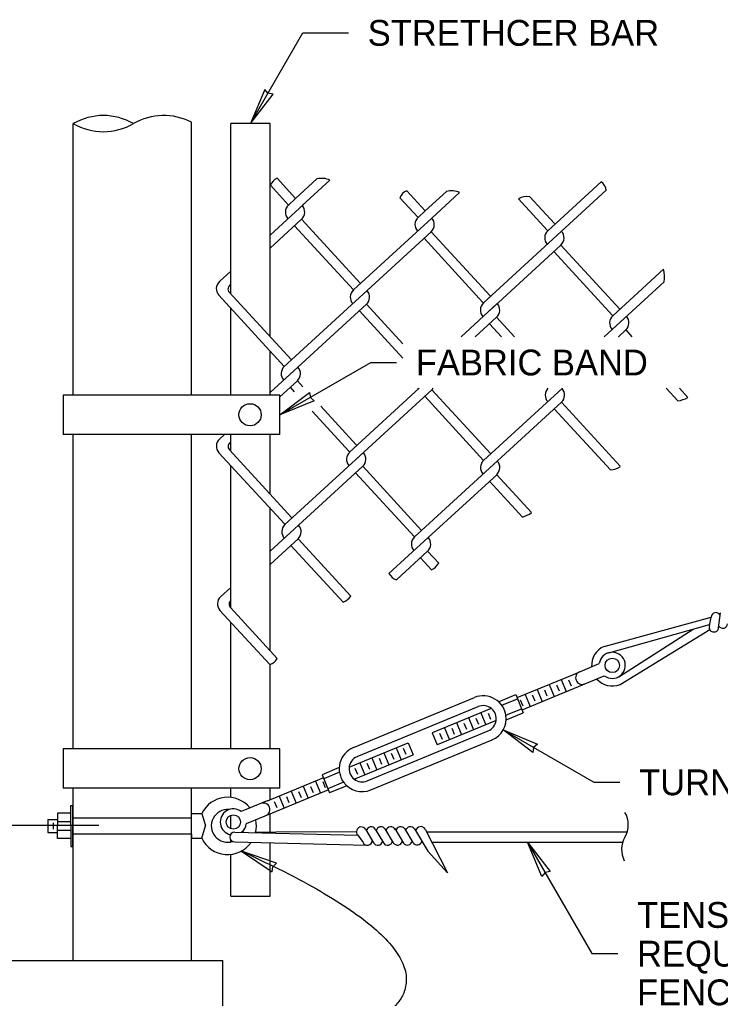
# Model space of a CAD drawing. Extents: x 99862 to 104211, y 98939 to 105076.
# Drawn here: x 100382 to 100816, y 103475 to 104082 of the extents above; entities that cross this region are included whole.
import ezdxf

# ---------------------------------------------------------------- set-up
doc = ezdxf.new("R2010")
doc.units = 0
for name, color, linetype in [('Level 15', 7, 'Continuous'), ('Level 2', 7, 'Continuous'), ('Level 20', 7, 'Continuous'), ('Level 4', 7, 'Continuous'), ('Level 7', 7, 'Continuous')]:
    doc.layers.add(name, color=color, linetype=linetype)

msp = doc.modelspace()

# ---------------------------------------------------------------- linework, layer by layer
at = {"layer": 'Level 15'}
for p, q in [((100524.69, 104017.94), (100557.19, 104074.23)), ((100557.19, 104074.23), (100573.19, 104074.23)), ((100569.42, 104074.23), (100585.42, 104074.23)), ((100542.99, 103837.25), (100599.28, 103869.75)), ((100599.28, 103869.75), (100615.28, 103869.75)), ((100681.43, 103641.84), (100737.72, 103609.34)), ((100737.72, 103609.34), (100753.72, 103609.34)), ((100430.77, 103582.48), (100322.08, 103582.48)), ((100696.53, 103572.2), (100736.45, 103503.07)), ((100736.45, 103503.07), (100752.45, 103503.07))]:
    msp.add_line(p, q, dxfattribs=at)
for points in [[(100524.69, 104017.94), (100538.69, 104036.22), (100535.57, 104036.79), (100533.52, 104039.2)], [(100542.99, 103837.25), (100561.27, 103851.25), (100561.84, 103848.13), (100564.25, 103846.08)], [(100681.43, 103641.84), (100702.69, 103633.01), (100700.29, 103630.95), (100699.71, 103627.84)], [(100696.53, 103572.2), (100710.53, 103553.93), (100707.42, 103553.35), (100705.36, 103550.94)], [(100519.1, 103566.7), (100538.16, 103553.78), (100538.56, 103556.92), (100540.84, 103559.11)]]:
    msp.add_lwpolyline(points, close=True, dxfattribs=at)
msp.add_open_spline([(100519.1, 103566.7), (100649.54, 103507.21), (100577.71, 103432.29), (100658.71, 103432.29)], degree=2, dxfattribs=at)
at = {"layer": 'Level 2'}
for p, q in [((100744.06, 103693.66), (100810.43, 103711.84)), ((100809.29, 103706.44), (100810.43, 103711.84)), ((100815.02, 103705.1), (100816.12, 103714.46)), ((100746.89, 103689.71), (100809.45, 103707.21)), ((100753.09, 103674.83), (100799.33, 103704.38)), ((100754.05, 103670.1), (100809.54, 103704.08)), ((100724.98, 103676.32), (100741, 103682.95)), ((100690, 103661.86), (100724.98, 103676.32)), ((100728.09, 103668.82), (100744.11, 103675.44)), ((100709.97, 103670.12), (100713.07, 103662.61)), ((100714.5, 103669.79), (100716.05, 103666.04)), ((100717.48, 103673.22), (100720.58, 103665.71)), ((100722.01, 103672.9), (100723.56, 103669.14)), ((100678.58, 103659.33), (100689.23, 103663.74)), ((100689.23, 103663.74), (100693.88, 103652.48)), ((100693.11, 103654.35), (100728.09, 103668.82)), ((100694.96, 103663.91), (100698.06, 103656.4)), ((100699.49, 103663.58), (100701.04, 103659.83)), ((100702.46, 103667.01), (100705.57, 103659.51)), ((100706.99, 103666.69), (100708.54, 103662.93)), ((100588.54, 103630.89), (100663.6, 103661.93)), ((100691.98, 103660.48), (100693.53, 103656.73)), ((100590.87, 103625.26), (100665.93, 103656.3)), ((100673.98, 103655.23), (100637.48, 103640.14)), ((100667.5, 103652.55), (100670.61, 103645.05)), ((100672.03, 103652.23), (100673.58, 103648.48)), ((100683.23, 103648.07), (100693.88, 103652.48)), ((100677.09, 103647.73), (100640.58, 103632.63)), ((100652.49, 103646.35), (100655.59, 103638.84)), ((100657.02, 103646.02), (100658.57, 103642.27)), ((100660, 103649.45), (100663.1, 103641.94)), ((100664.52, 103649.13), (100666.08, 103645.37)), ((100597.07, 103610.25), (100672.2, 103641.31)), ((100637.48, 103640.14), (100640.58, 103632.63)), ((100642.01, 103639.81), (100643.56, 103636.06)), ((100644.98, 103643.24), (100648.09, 103635.74)), ((100649.51, 103642.92), (100651.06, 103639.16)), ((100585.96, 103618.83), (100622.46, 103633.93)), ((100599.4, 103604.62), (100674.54, 103635.69)), ((100622.46, 103633.93), (100625.57, 103626.42)), ((100589.06, 103611.33), (100625.57, 103626.42)), ((100607.45, 103627.72), (100610.55, 103620.22)), ((100611.98, 103627.4), (100613.53, 103623.64)), ((100614.96, 103630.83), (100618.06, 103623.32)), ((100619.49, 103630.5), (100621.04, 103626.75)), ((100592.44, 103621.51), (100595.54, 103614.01)), ((100596.97, 103621.19), (100598.52, 103617.44)), ((100599.94, 103624.62), (100603.05, 103617.11)), ((100604.47, 103624.29), (100606.02, 103620.54)), ((100579.77, 103618.48), (100569.12, 103614.07)), ((100589.46, 103618.09), (100591.01, 103614.33)), ((100569.9, 103612.19), (100534.96, 103597.75)), ((100564.98, 103610.16), (100568.09, 103602.65)), ((100569.12, 103614.07), (100573.78, 103602.81)), ((100569.51, 103609.84), (100571.06, 103606.08)), ((100573, 103604.69), (100538.06, 103590.24)), ((100549.97, 103603.95), (100553.07, 103596.45)), ((100554.5, 103603.63), (100556.05, 103599.88)), ((100557.48, 103607.06), (100560.58, 103599.55)), ((100562, 103606.73), (100563.56, 103602.98)), ((100584.43, 103607.22), (100573.78, 103602.81)), ((100535.04, 103597.78), (100519.02, 103591.16)), ((100539.49, 103597.42), (100541.04, 103593.67)), ((100542.46, 103600.85), (100545.57, 103593.34)), ((100546.99, 103600.52), (100548.54, 103596.77)), ((100405.1, 103590.16), (100405.1, 103582.28)), ((100538.15, 103590.27), (100522.13, 103583.65)), ((100399.13, 103586.34), (100399.13, 103578.22)), ((100399.13, 103586.34), (100405.1, 103586.34)), ((100402.29, 103584.31), (100402.29, 103580.25)), ((100405.15, 103584.99), (100413.32, 103584.99)), ((100414.77, 103587.37), (100488.04, 103587.37)), ((100494.52, 103589.91), (100496.87, 103582.29)), ((100399.13, 103578.22), (100405.1, 103578.22)), ((100405.05, 103579.58), (100413.32, 103579.58)), ((100405.1, 103574.41), (100405.1, 103582.28)), ((100494.52, 103574.68), (100496.87, 103582.29)), ((100515.09, 103578.44), (100591.19, 103576.6)), ((100527.94, 103578.52), (100540.61, 103578.6)), ((100540.61, 103578.6), (100590.46, 103578.91)), ((100596.06, 103580.22), (100600.99, 103571.82)), ((100602.1, 103580.35), (100607.17, 103571.75)), ((100608.11, 103580.51), (100613.27, 103571.87)), ((100614.14, 103580.63), (100619.62, 103571.57)), ((100620.27, 103580.61), (100625.44, 103572.01)), ((100626.44, 103580.55), (100634.69, 103566.63)), ((100633.02, 103580.22), (100646.84, 103553.24)), ((100633.87, 103578.55), (100758.28, 103578.54)), ((100488.04, 103577.21), (100414.77, 103577.21)), ((100514.94, 103572.34), (100596.49, 103570.37)), ((100591.2, 103576.58), (100594.51, 103571.94)), ((100637.12, 103572.21), (100755.52, 103572.2)), ((100634.69, 103566.63), (100646.84, 103553.24))]:
    msp.add_line(p, q, dxfattribs=at)
for points in [[(100680.54, 103657.15), (100690.28, 103661.18)], [(100683.08, 103651), (100692.82, 103655.03)], [(100579.93, 103615.54), (100570.18, 103611.51)], [(100582.47, 103609.4), (100572.72, 103605.37)], [(100413.32, 103582.28), (100413.32, 103590.16), (100405.1, 103590.16)], [(100413.32, 103590.16), (100413.32, 103595.03), (100414.54, 103595.03)], [(100413.32, 103574.41), (100413.32, 103569.54), (100414.54, 103569.54), (100414.54, 103595.03)], [(100488.04, 103587.37), (100488.04, 103589.91), (100494.52, 103589.91)], [(100413.32, 103582.28), (100413.32, 103574.41), (100405.1, 103574.41)], [(100488.04, 103577.21), (100488.04, 103574.68), (100494.52, 103574.68)]]:
    msp.add_lwpolyline(points, dxfattribs=at)
for centre in [(100749.05, 103681.88), (100514.08, 103584.72)]:
    msp.add_circle(centre, 4.47, dxfattribs=at)
for centre, radius, start, end in [((100813.37, 103711.66), 2.95, 28.55995, 176.50822), ((100812.1, 103705.54), 2.95, 162.2466, 355.13036), ((100817.52, 103707.87), 2.95, 216.19353, 356.79864), ((100749.05, 103681.88), 12.8, 112.96867, 183.96114), ((100749.05, 103681.88), 8.12, 232.46575, 172.46575), ((100730.37, 103674.16), 4.06, 112.46575, 292.46575), ((100749.05, 103681.88), 12.8, 220.97036, 292.96867), ((100669.03, 103648.79), 14.22, 6.15322, 112.46765), ((100669.03, 103648.79), 8.12, 349.38086, 112.46754), ((100669.03, 103648.79), 14.22, 292.46575, 8.94198), ((100669.03, 103648.79), 8.12, 292.46575, 352.46441), ((100593.97, 103617.75), 14.22, 112.46385, 217.98282), ((100593.97, 103617.75), 8.12, 112.46396, 241.57185), ((100593.97, 103617.75), 14.22, 215.9905, 292.46575), ((100593.97, 103617.75), 8.12, 232.46575, 292.46575), ((100510.58, 103582.29), 17.77, 38.69447, 154.62307), ((100532.75, 103592.44), 4.06, 292.46575, 112.46575), ((100510.58, 103582.29), 10.15, 85.01859, 287.42988), ((100514.08, 103584.72), 8.12, 52.46575, 256.90582), ((100743.6, 103583.03), 15.35, 330, 30), ((100510.58, 103582.29), 17.77, 346.44895, 12.23165), ((100514.92, 103575.39), 3.05, 90.3612, 270.3612), ((100514.08, 103584.72), 8.12, 309.02747, 352.46575), ((100510.58, 103582.29), 10.15, 337.50578, 344.44411), ((100593.49, 103578.6), 3.05, 32.2514, 221.40065), ((100599.58, 103578.64), 3.05, 34.22449, 167.45372), ((100605.67, 103578.67), 3.05, 36.98401, 167.51131), ((100611.77, 103578.71), 3.05, 23.53144, 167.6433), ((100617.86, 103578.75), 3.05, 37.67326, 167.76298), ((100623.96, 103578.79), 3.05, 35.2348, 167.68417), ((100630.3, 103578.83), 3.05, 27.11893, 173.95764), ((100510.58, 103582.29), 17.77, 205.37693, 324.62168), ((100597.22, 103573.33), 3.05, 207.13903, 355.0873), ((100603.62, 103573.37), 3.05, 210.43814, 347.5653), ((100609.73, 103573.41), 3.05, 212.94547, 348.58451), ((100615.89, 103573.45), 3.06, 210.96407, 347.75914), ((100622, 103573.49), 3.05, 218.89033, 347.06072), ((100628.06, 103573.59), 3.05, 211.0453, 345.70958), ((100770.19, 103567.67), 15.35, 150, 206.99342)]:
    msp.add_arc(centre, radius, start, end, dxfattribs=at)
at = {"layer": 'Level 4'}
for p, q in [((100537.07, 103979.67), (100548.31, 103967.42)), ((100541.25, 103984), (100552.73, 103971.48)), ((100565.95, 103983.61), (100552.73, 103971.48)), ((100574.01, 103982.86), (100556.79, 103967.06)), ((100742.18, 103981.81), (100709.12, 103951.47)), ((100621.6, 103976.31), (100633.09, 103963.8)), ((100646.3, 103975.93), (100633.09, 103963.8)), ((100654.36, 103975.18), (100637.15, 103959.38)), ((100745.35, 103976.57), (100669.22, 103906.69)), ((100697.9, 103972.56), (100713.2, 103955.89)), ((100557.57, 103967.77), (100536.92, 103948.82)), ((100552.73, 103971.48), (100548.31, 103967.42)), ((100617.42, 103971.99), (100628.67, 103959.74)), ((100690.87, 103971.35), (100708.78, 103951.83)), ((100633.09, 103963.8), (100628.67, 103959.74)), ((100556.43, 103958.58), (100536.92, 103940.67)), ((100552.01, 103954.53), (100588.52, 103914.74)), ((100556.43, 103958.58), (100592.94, 103918.8)), ((100637.15, 103959.38), (100588.52, 103914.74)), ((100713.2, 103955.89), (100713.54, 103955.52)), ((100636.78, 103950.9), (100550.09, 103871.32)), ((100628.31, 103951.26), (100628.31, 103951.26)), ((100636.78, 103950.9), (100673.3, 103911.12)), ((100708.78, 103951.83), (100709.12, 103951.47)), ((100632.36, 103946.84), (100668.88, 103907.06)), ((100717.24, 103942.63), (100673.27, 103902.27)), ((100708.76, 103942.99), (100708.76, 103942.99)), ((100717.24, 103942.63), (100753.75, 103902.84)), ((100712.82, 103938.57), (100749.33, 103898.79)), ((100512.49, 103926.39), (100505.46, 103919.94)), ((100780.76, 103927.64), (100749.33, 103898.79)), ((100781.16, 103919.86), (100744, 103885.75)), ((100511.55, 103913.31), (100550.09, 103871.32)), ((100505.1, 103911.47), (100545.67, 103867.26)), ((100596.64, 103905.9), (100554.15, 103866.9)), ((100588.16, 103906.27), (100588.16, 103906.27)), ((100596.64, 103905.9), (100619.28, 103881.24)), ((100677.69, 103906.33), (100655.27, 103885.75)), ((100668.88, 103907.06), (100669.22, 103906.69)), ((100673.64, 103910.75), (100669.22, 103906.69)), ((100673.3, 103911.12), (100673.64, 103910.75)), ((100592.22, 103901.85), (100619.28, 103872.37)), ((100677.33, 103897.85), (100664.15, 103885.75)), ((100668.85, 103898.21), (100668.85, 103898.21)), ((100672.91, 103893.79), (100680.3, 103885.75)), ((100677.33, 103897.85), (100688.44, 103885.75)), ((100748.97, 103890.31), (100748.97, 103890.31)), ((100757.45, 103889.95), (100752.87, 103885.75)), ((100757.45, 103889.95), (100761.3, 103885.75)), ((100753.03, 103885.89), (100753.16, 103885.75)), ((100550.09, 103871.32), (100545.67, 103867.26)), ((100554.15, 103866.9), (100536.92, 103851.08)), ((100553.79, 103858.42), (100542.99, 103848.51)), ((100553.79, 103858.42), (100557.21, 103854.69)), ((100549.37, 103854.37), (100551.89, 103851.62)), ((100629.28, 103853.75), (100586.22, 103814.22)), ((100637.19, 103852.86), (100590.28, 103809.8)), ((100628.71, 103853.22), (100628.71, 103853.22)), ((100637.19, 103852.86), (100673.7, 103813.08)), ((100717.91, 103853.65), (100669.28, 103809.02)), ((100718.01, 103853.75), (100717.91, 103853.65)), ((100782.53, 103853.75), (100789.67, 103845.97)), ((100790.68, 103853.75), (100795.93, 103848.02)), ((100717.54, 103845.17), (100630.85, 103765.6)), ((100632.77, 103848.8), (100669.28, 103809.02)), ((100709.06, 103845.53), (100709.06, 103845.53)), ((100717.54, 103845.17), (100754.06, 103805.39)), ((100562.97, 103839.55), (100585.88, 103814.59)), ((100568.29, 103842.62), (100590.3, 103818.64)), ((100713.12, 103841.11), (100747.96, 103803.16)), ((100508.54, 103825.03), (100505.53, 103822.27)), ((100511.61, 103815.64), (100550.16, 103773.65)), ((100590.64, 103818.27), (100586.22, 103814.22)), ((100590.3, 103818.64), (100590.64, 103818.27)), ((100505.16, 103813.79), (100545.74, 103769.59)), ((100594.7, 103813.85), (100546.08, 103769.22)), ((100594.33, 103805.38), (100536.92, 103752.67)), ((100594.33, 103805.38), (100630.85, 103765.6)), ((100589.91, 103801.32), (100626.43, 103761.54)), ((100677.4, 103800.18), (100634.91, 103761.18)), ((100677.4, 103800.18), (100698.95, 103776.7)), ((100672.98, 103796.12), (100693.39, 103773.89)), ((100554.19, 103760.38), (100536.92, 103744.53)), ((100545.71, 103760.75), (100545.71, 103760.75)), ((100554.19, 103760.38), (100586.91, 103724.74)), ((100634.91, 103761.18), (100610.6, 103738.86)), ((100630.85, 103765.6), (100626.43, 103761.54)), ((100549.77, 103756.33), (100582.13, 103721.07)), ((100634.55, 103752.7), (100615.24, 103734.98)), ((100626.07, 103753.06), (100626.07, 103753.06)), ((100630.13, 103748.64), (100637.07, 103741.08)), ((100634.55, 103752.7), (100641.42, 103745.21)), ((100512.49, 103730.25), (100506.17, 103724.45)), ((100512.26, 103717.82), (100541.28, 103686.2)), ((100505.81, 103715.97), (100536.67, 103682.35))]:
    msp.add_line(p, q, dxfattribs=at)
for centre, radius, start, end in [((100544.24, 103976.93), 7.68, 112.93426, 159.03017), ((100568.93, 103971.99), 12, 64.99857, 104.40024), ((100738.11, 103975.78), 7.28, 6.23281, 55.96723), ((100624.59, 103969.24), 7.68, 112.93426, 159.03017), ((100649.29, 103964.3), 12, 64.99857, 104.40024), ((100696.34, 103960.66), 12, 82.53429, 117.102), ((100552.37, 103963), 6, 132.54951, 222.54951), ((100552.37, 103963), 6, 312.54951, 42.54951), ((100632.73, 103955.32), 6, 132.54951, 222.54951), ((100632.73, 103955.32), 6, 312.54951, 42.54951), ((100713.18, 103947.05), 6, 132.54951, 222.54951), ((100713.18, 103947.05), 6, 312.54951, 42.54951), ((100762.61, 103922.8), 18.78, 350.98302, 14.91191), ((100509.52, 103915.52), 6, 132.54951, 222.54951), ((100513.76, 103915.34), 3, 115.01845, 222.54951), ((100592.58, 103910.32), 6, 132.54951, 222.54951), ((100592.58, 103910.32), 6, 312.54951, 42.54951), ((100673.27, 103902.27), 6, 132.54951, 222.54951), ((100673.27, 103902.27), 6, 312.54951, 42.54951), ((100753.39, 103894.37), 6, 132.54951, 222.54951), ((100753.39, 103894.37), 6, 312.54951, 42.54951), ((100549.73, 103862.84), 6, 132.54951, 222.54951), ((100549.73, 103862.84), 6, 312.54951, 42.54951), ((100633.13, 103857.28), 6, 216.04484, 222.54951), ((100633.13, 103857.28), 6, 312.54951, 323.95516), ((100713.49, 103849.59), 6, 136.1739, 222.54951), ((100713.49, 103849.59), 6, 312.54951, 42.54951), ((100787.05, 103864.57), 18.78, 278.01652, 298.22414), ((100509.58, 103817.85), 6, 132.54951, 222.54951), ((100513.82, 103817.67), 3, 116.43008, 222.54951), ((100590.28, 103809.8), 6, 132.54951, 222.54951), ((100590.28, 103809.8), 6, 312.54951, 42.54951), ((100673.34, 103804.6), 6, 132.54951, 222.54951), ((100673.34, 103804.6), 6, 312.54951, 42.54951), ((100745.35, 103821.75), 18.78, 278.01652, 298.22414), ((100690.28, 103786.94), 13.42, 283.39981, 310.25678), ((100550.13, 103764.8), 6, 132.54951, 222.54951), ((100550.13, 103764.8), 6, 312.54951, 42.54951), ((100630.49, 103757.12), 6, 132.54951, 222.54951), ((100630.49, 103757.12), 6, 312.54951, 42.54951), ((100630.23, 103752.63), 13.42, 300.64138, 326.48003), ((100618.01, 103743.01), 8.49, 209.22637, 250.97872), ((100510.23, 103720.03), 6, 132.54951, 222.54951), ((100577.45, 103732.09), 11.97, 293.00373, 322.14624), ((100514.47, 103719.85), 3, 131.26141, 222.54951), ((100533.78, 103690.49), 8.64, 289.52536, 330.19955)]:
    msp.add_arc(centre, radius, start, end, dxfattribs=at)
at = {"layer": 'Level 7'}
for p, q in [((100414.77, 103849.46), (100414.77, 104017.94)), ((100488.06, 103849.46), (100488.06, 104018.78)), ((100536.92, 104017.94), (100512.49, 104017.94)), ((100512.49, 103912.29), (100512.49, 104017.94)), ((100536.92, 103885.68), (100536.92, 104017.94)), ((100512.49, 103849.46), (100512.49, 103903.42)), ((100536.92, 103849.46), (100536.92, 103876.8)), ((100542.99, 103849.46), (100408.63, 103849.46)), ((100408.63, 103849.46), (100408.63, 103825.03)), ((100542.99, 103825.03), (100542.99, 103849.46)), ((100542.99, 103825.03), (100408.63, 103825.03)), ((100414.77, 103630.09), (100414.77, 103825.03)), ((100488.06, 103630.09), (100488.06, 103825.03)), ((100512.49, 103814.69), (100512.49, 103825.03)), ((100536.92, 103788.08), (100536.92, 103825.03)), ((100512.49, 103717.57), (100512.49, 103805.82)), ((100536.92, 103690.95), (100536.92, 103779.2)), ((100512.49, 103630.09), (100512.49, 103708.69)), ((100536.92, 103630.09), (100536.92, 103682.44)), ((100542.99, 103630.09), (100408.63, 103630.09)), ((100408.63, 103630.09), (100408.63, 103605.66)), ((100542.99, 103605.66), (100542.99, 103630.09)), ((100542.99, 103605.66), (100408.63, 103605.66)), ((100414.77, 103498.91), (100414.77, 103605.66)), ((100488.06, 103498.91), (100488.06, 103605.66)), ((100512.49, 103599.96), (100512.49, 103605.66)), ((100536.92, 103598.56), (100536.92, 103605.66)), ((100512.49, 103580.54), (100512.49, 103588.89)), ((100536.92, 103578.41), (100536.92, 103589.77)), ((100512.49, 103572.32), (100512.49, 103573.52)), ((100536.92, 103538.74), (100536.92, 103571.64)), ((100512.49, 103538.74), (100512.49, 103564.62)), ((100512.49, 103538.74), (100536.92, 103538.74)), ((100292.63, 103498.91), (100507.6, 103498.91)), ((100507.6, 103467.16), (100507.6, 103498.91))]:
    msp.add_line(p, q, dxfattribs=at)
for centre in [(100524.48, 103837.33), (100524.48, 103617.81)]:
    msp.add_circle(centre, 6.89, dxfattribs=at)
for centre, start, end in [((100433.48, 103985.54), 60, 120), ((100470.89, 103985.54), 62.67329, 120), ((100433.48, 104050.34), 240, 300)]:
    msp.add_arc(centre, 37.41, start, end, dxfattribs=at)

# ---------------------------------------------------------------- texts
at = {"layer": 'Level 20'}
for s, p in [('STRETHCER BAR', (100597.42, 104066.23)), ('FABRIC BAND', (100627.28, 103861.75)), ('TURNBUCKLE', (100765.72, 103601.34)), ('TENSION WIRE (TYP.) (NOT', (100764.45, 103519.07)), ('REQUIRED FOR CHAIN LINK', (100764.45, 103495.07)), ('FENCE TYPE 4)', (100764.45, 103471.07))]:
    msp.add_text(s, height=16, dxfattribs=at).set_placement(p)

doc.saveas('drawing.dxf')
